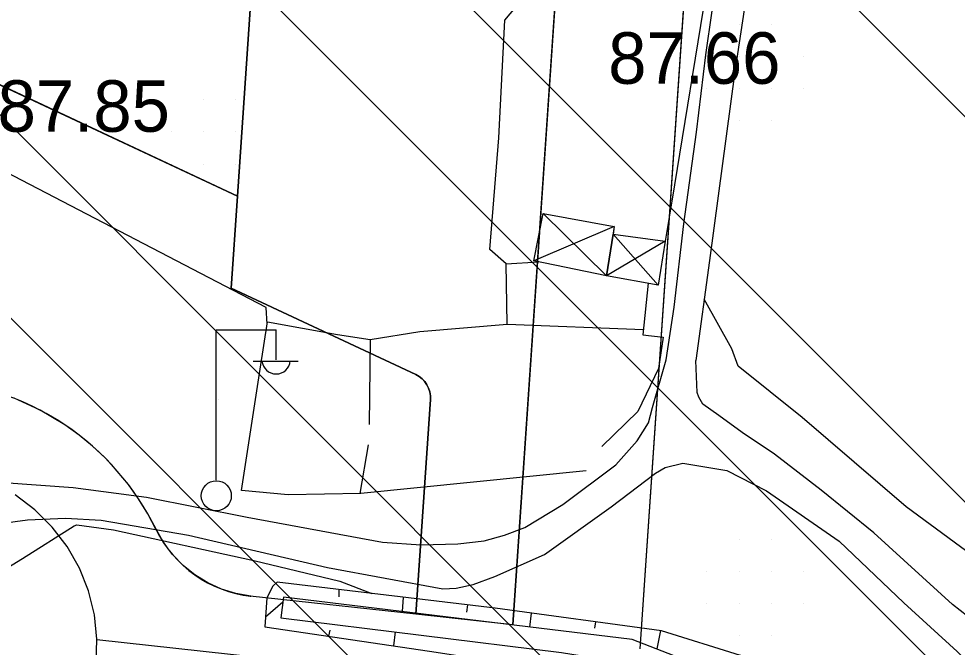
# Model space of a CAD drawing. Extents: x 417995 to 421451, y 4454518 to 4458015.
# Drawn here: x 420928.1 to 421037.5, y 4455671.2 to 4455744.4 of the extents above; entities that cross this region are included whole.
import ezdxf

# ---------------------------------------------------------------- set-up
doc = ezdxf.new("R2010")
doc.units = 0
for name, color, linetype in [('ADAKENARI', 7, 'Continuous'), ('B_Betonzemin', 7, 'Continuous'), ('B_Kapi', 7, 'Continuous'), ('B_Sundurma', 7, 'Continuous'), ('KALDIRIM_FAT', 7, 'Continuous'), ('PL_K_BHA', 7, 'Continuous'), ('PL_T_GUNUBIRLIK', 7, 'Continuous'), ('PL_TA_K_OTOPARK', 7, 'Continuous'), ('S_Elektrik_Diregi', 7, 'Continuous'), ('Sev_Sevalti', 7, 'Continuous'), ('Sev_Sevustu', 7, 'Continuous'), ('Sev_Tarama', 7, 'Continuous'), ('Sinir_Cit_bir_taraf', 7, 'Continuous'), ('Sinir_itirazli_Mulkiyet', 7, 'Continuous'), ('Sinir_Tel_bir_taraf', 7, 'Continuous'), ('SN_TR_SIVILASMA', 7, 'Continuous'), ('TRFAT_BHA', 7, 'Continuous'), ('TRFAT_GUNUBİRLİK', 7, 'Continuous'), ('Y_Kot_Noktasi', 7, 'Continuous'), ('Y_Yol_Kotu', 7, 'Continuous'), ('Yol_Toprak_Duz', 7, 'Continuous'), ('Yol_Toprak_Kesik', 7, 'Continuous')]:
    doc.layers.add(name, color=color, linetype=linetype)

msp = doc.modelspace()

# ---------------------------------------------------------------- linework, layer by layer
at = {"layer": 'ADAKENARI'}
for p, q in [((420953.63, 4455723.77), (420963.07, 4455862.75)), ((420985.73, 4455673.85), (420995.32, 4455815.13)), ((421000.57, 4455671.04), (421010.29, 4455814.11)), ((420915.24, 4455741.74), (420953.63, 4455723.77)), ((420952.9, 4455713.07), (420953.63, 4455723.77)), ((420952.9, 4455713.07), (420974.4, 4455703)), ((420976.12, 4455700.08), (420974.43, 4455675.09)), ((420974.43, 4455675.09), (420955.12, 4455677.19)), ((420985.73, 4455673.85), (420974.43, 4455675.09))]:
    msp.add_line(p, q, dxfattribs=at)
for centre, radius, start, end in [((420916.26, 4455671.38), 31, 56.2175, 105.5206), ((420973.13, 4455700.28), 3, 356.1139, 64.9143), ((420916.26, 4455671.38), 31, 26.002, 56.2175), ((420956.71, 4455691.11), 14, 206.002, 263.771)]:
    msp.add_arc(centre, radius, start, end, dxfattribs=at)
at = {"layer": 'B_Betonzemin'}
msp.add_lwpolyline([(421067.72, 4455631.25), (421023.32, 4455660.48), (421015.05, 4455665.86), (421009.41, 4455668.33), (420999.62, 4455672.15), (420958.99, 4455677.06), (420958.67, 4455674.65), (420991.4, 4455670.63), (421000.3, 4455669.19), (421010.57, 4455665.18), (421038.73, 4455646.9), (421060.73, 4455631.09)], dxfattribs=at)
at = {"layer": 'B_Kapi'}
msp.add_lwpolyline([(420925.1, 4455679.46), (420928.57, 4455681.57)], dxfattribs=at)
at = {"layer": 'B_Sundurma'}
for p, q in [((420989.25, 4455721.75), (420996.66, 4455714.48)), ((420997.54, 4455720.24), (420988.18, 4455716.25)), ((421003.49, 4455718.55), (420996.66, 4455714.48)), ((420997.41, 4455719.37), (421002.67, 4455713.42))]:
    msp.add_line(p, q, dxfattribs=at)
for points in [[(420989.25, 4455721.75), (420997.54, 4455720.24), (420996.66, 4455714.48), (420988.18, 4455716.25)], [(420997.41, 4455719.37), (420996.66, 4455714.48), (420988.18, 4455716.25), (420989.25, 4455721.75), (420997.54, 4455720.24)], [(420997.41, 4455719.37), (421003.49, 4455718.55), (421002.67, 4455713.42), (420996.66, 4455714.48)], [(420997.41, 4455719.37), (421003.49, 4455718.55), (421002.67, 4455713.42), (420996.66, 4455714.48)]]:
    msp.add_lwpolyline(points, close=True, dxfattribs=at)
at = {"layer": 'KALDIRIM_FAT'}
for p, q in [((420930.01, 4455687.25), (420927.72, 4455688.98)), ((420932.04, 4455685.23), (420930.01, 4455687.25)), ((420933.78, 4455682.96), (420932.04, 4455685.23)), ((420935.2, 4455680.46), (420933.78, 4455682.96)), ((420936.26, 4455677.8), (420935.2, 4455680.46)), ((420936.95, 4455675.02), (420936.26, 4455677.8)), ((420937.25, 4455672.17), (420936.95, 4455675.02)), ((420937.16, 4455669.3), (420937.25, 4455672.17)), ((420987.8, 4455666.58), (420937.25, 4455672.1))]:
    msp.add_line(p, q, dxfattribs=at)
at = {"layer": 'PL_K_BHA'}
msp.add_lwpolyline([(420915.24, 4455741.74), (420953.63, 4455723.77), (420952.9, 4455713.07), (420974.4, 4455703), (420974.4, 4455703), (420974.79, 4455702.78), (420975.15, 4455702.5), (420975.46, 4455702.18), (420975.71, 4455701.81), (420975.91, 4455701.4), (420976.05, 4455700.98), (420976.12, 4455700.53), (420976.12, 4455700.08), (420976.12, 4455700.08), (420974.43, 4455675.09), (420955.12, 4455677.19), (420955.19, 4455677.19), (420953.45, 4455677.49), (420951.77, 4455678.01), (420950.16, 4455678.73), (420948.66, 4455679.65), (420947.28, 4455680.76), (420946.05, 4455682.02), (420945, 4455683.44), (420944.13, 4455684.97), (420944.13, 4455684.97), (420943.17, 4455686.78), (420942.1, 4455688.51), (420940.91, 4455690.18), (420939.62, 4455691.76), (420938.23, 4455693.26), (420936.74, 4455694.66), (420935.16, 4455695.95), (420933.5, 4455697.14), (420933.5, 4455697.14), (420930.64, 4455698.85), (420927.6, 4455700.23)], dxfattribs=at)
at = {"layer": 'PL_T_GUNUBIRLIK'}
for points in [[(420918.4, 4455889.24), (420925.14, 4455884.18), (420932.12, 4455879.46), (420939.33, 4455875.09), (420946.74, 4455871.07), (420963.07, 4455862.75), (420953.63, 4455723.77), (420915.24, 4455741.74), (420902.71, 4455747.61), (420837.21, 4455780.99), (420826.46, 4455771.47), (420807.44, 4455792.93), (420792.16, 4455812.19), (420746.55, 4455881.28), (420710.3, 4455994.37)], [(421000.57, 4455671.04), (421010.29, 4455814.11), (421010.42, 4455819.17), (421010.13, 4455824.23), (421009.42, 4455829.24), (421008.3, 4455834.18), (421006.77, 4455839.01), (421004.84, 4455843.69), (421002.53, 4455848.19), (420999.85, 4455852.49), (420996.82, 4455856.55), (420993.47, 4455860.34), (420989.81, 4455863.84), (420985.87, 4455867.02), (420981.68, 4455869.87), (420977.27, 4455872.35), (420953.55, 4455884.44), (420946.79, 4455888.1)]]:
    msp.add_lwpolyline(points, dxfattribs=at)
at = {"layer": 'PL_TA_K_OTOPARK'}
msp.add_lwpolyline([(420995.32, 4455815.13), (420985.73, 4455673.85), (420974.43, 4455675.09), (420976.12, 4455700.08), (420976.12, 4455700.08), (420976.12, 4455700.53), (420976.05, 4455700.98), (420975.91, 4455701.4), (420975.71, 4455701.81), (420975.46, 4455702.18), (420975.15, 4455702.5), (420974.79, 4455702.78), (420974.4, 4455703), (420974.4, 4455703), (420952.9, 4455713.07), (420953.63, 4455723.77), (420963.07, 4455862.75)], dxfattribs=at)
at = {"layer": 'S_Elektrik_Diregi'}
for p, q in [((420951.13, 4455690.71), (420951.13, 4455708.21)), ((420951.13, 4455708.21), (420958.13, 4455708.21)), ((420958.13, 4455704.71), (420958.13, 4455708.21)), ((420955.47, 4455704.57), (420960.72, 4455704.57))]:
    msp.add_line(p, q, dxfattribs=at)
msp.add_circle((420951.16, 4455688.88), 1.75, dxfattribs=at)
msp.add_arc((420958.13, 4455704.73), 1.66, 184.8384, 355.1464, dxfattribs=at)
at = {"layer": 'Sev_Sevalti'}
msp.add_lwpolyline([(421060.73, 4455631.09), (421064.37, 4455628.47), (421079.78, 4455617.97), (421080.48, 4455618.07), (421081.95, 4455620.68), (421081.67, 4455621.39), (421067.72, 4455631.25), (421023.32, 4455660.48), (421015.05, 4455665.86), (421009.41, 4455668.33), (420999.62, 4455672.15), (420958.99, 4455677.06), (420958.67, 4455674.65), (420991.4, 4455670.63), (421000.3, 4455669.19), (421010.57, 4455665.18), (421038.73, 4455646.9), (421060.73, 4455631.09)], dxfattribs=at)
at = {"layer": 'Sev_Sevustu'}
msp.add_lwpolyline([(421084.77, 4455617.56), (421084.03, 4455621.15), (421058.97, 4455638.82), (421028.96, 4455658.53), (421012.25, 4455670.27), (421003.07, 4455673.15), (420983.66, 4455675.79), (420958.26, 4455678.82), (420957.73, 4455678.35), (420957.05, 4455677), (420956.83, 4455673.6), (420976.02, 4455670.79), (421002.11, 4455666.78), (421005.9, 4455665.86), (421016.69, 4455659.45), (421046.16, 4455638.4), (421079.97, 4455615.75), (421081.98, 4455615.46), (421083.52, 4455615.87), (421084.77, 4455617.56)], dxfattribs=at)
at = {"layer": 'Sev_Tarama'}
for p, q in [((420965.44, 4455677.97), (420965.44, 4455677.12)), ((420972.95, 4455677.07), (420972.82, 4455675.39)), ((420956.9, 4455674.79), (420958.92, 4455676.53)), ((420980.42, 4455676.18), (420980.33, 4455675.33)), ((420987.88, 4455675.22), (420987.68, 4455673.59)), ((420995.35, 4455674.2), (420995.24, 4455673.45)), ((420964.28, 4455672.51), (420964.43, 4455673.22)), ((420971.84, 4455671.4), (420972.05, 4455673.01)), ((421002.95, 4455673.17), (421002.5, 4455671.03))]:
    msp.add_line(p, q, dxfattribs=at)
at = {"layer": 'Sinir_Cit_bir_taraf'}
for points in [[(421009.97, 4455770.25), (421011.59, 4455769.85), (421008.51, 4455749.18), (421004.26, 4455723.19)], [(420984.94, 4455715.9), (420983.04, 4455717.55), (420984.1, 4455730.59), (420984.79, 4455744.27), (420986.05, 4455745.75), (420986.86, 4455758.27), (420988.26, 4455762.12)], [(420957.08, 4455708.88), (420956.97, 4455710.81), (420923.7, 4455728.09), (420914.51, 4455730.8)], [(421004.26, 4455723.19), (421003.49, 4455718.55)], [(420994.27, 4455691.79), (420968, 4455689.14), (420959.55, 4455688.97), (420954.09, 4455689.49), (420956.28, 4455703.63), (420957.12, 4455709.15), (420965.29, 4455707.67), (420969.11, 4455707.07), (420974.87, 4455708.02), (420985.05, 4455708.86), (420984.94, 4455715.9), (420988.72, 4455716.14)], [(421001.51, 4455713.63), (421000.89, 4455707.62), (421003.23, 4455707.37), (421002.72, 4455703.72), (421000.31, 4455698.68), (420996.09, 4455694.63)], [(420985.05, 4455708.86), (421000.95, 4455708.24)], [(420969.11, 4455707.07), (420968.99, 4455697.19)], [(420968.87, 4455694.82), (420967.89, 4455689.14)]]:
    msp.add_lwpolyline(points, dxfattribs=at)
at = {"layer": 'Sinir_itirazli_Mulkiyet'}
msp.add_lwpolyline([(421047.02, 4455676.2), (421031.56, 4455687.58), (421019.46, 4455697.98), (421011.97, 4455703.98), (421011.25, 4455705.98), (421008.03, 4455711.78)], dxfattribs=at)
at = {"layer": 'Sinir_Tel_bir_taraf'}
msp.add_lwpolyline([(420928.57, 4455681.57), (420934.59, 4455685.36), (420934.9, 4455685.51), (420939.18, 4455684.9), (420955.52, 4455681.35), (420965.56, 4455678.95), (420969.28, 4455677.51)], dxfattribs=at)
at = {"layer": 'SN_TR_SIVILASMA'}
for p, q in [((421271.63, 4455499.84), (420239.54, 4456531.93)), ((421271.16, 4455455.4), (420227.3, 4456499.27)), ((421270.93, 4455433.18), (420221.05, 4456483.06)), ((421270.47, 4455388.74), (420206.08, 4456453.13)), ((421270.24, 4455366.53), (420198.6, 4456438.16))]:
    msp.add_line(p, q, dxfattribs=at)
at = {"layer": 'TRFAT_BHA'}
msp.add_line((420951.46, 4455700.09), (420951.46, 4455700.09), dxfattribs=at)
at = {"layer": 'TRFAT_GUNUBİRLİK'}
for p, q in [((421012.1, 4455743.82), (421012.1, 4455743.82)), ((421015.85, 4455743.82), (421015.85, 4455743.82)), ((421008.35, 4455740.07), (421008.35, 4455740.07)), ((421012.1, 4455740.07), (421012.1, 4455740.07)), ((421015.85, 4455740.07), (421015.85, 4455740.07)), ((421019.6, 4455740.07), (421019.6, 4455740.07)), ((421008.35, 4455736.32), (421008.35, 4455736.32)), ((421012.1, 4455736.32), (421012.1, 4455736.32)), ((421015.85, 4455736.32), (421015.85, 4455736.32)), ((421019.6, 4455736.32), (421019.6, 4455736.32)), ((420949.7, 4455735.02), (420949.7, 4455735.02)), ((420953.45, 4455735.02), (420953.45, 4455735.02)), ((421012.1, 4455732.57), (421012.1, 4455732.57)), ((421015.85, 4455732.57), (421015.85, 4455732.57)), ((420945.95, 4455731.27), (420945.95, 4455731.27)), ((420949.7, 4455731.27), (420949.7, 4455731.27)), ((420953.45, 4455731.27), (420953.45, 4455731.27)), ((420945.95, 4455727.52), (420945.95, 4455727.52)), ((420949.7, 4455727.52), (420949.7, 4455727.52)), ((420953.45, 4455727.52), (420953.45, 4455727.52)), ((421012.1, 4455683.82), (421012.1, 4455683.82)), ((421015.85, 4455683.82), (421015.85, 4455683.82)), ((421008.35, 4455680.07), (421008.35, 4455680.07)), ((421012.1, 4455680.07), (421012.1, 4455680.07)), ((421015.85, 4455680.07), (421015.85, 4455680.07)), ((421019.6, 4455680.07), (421019.6, 4455680.07)), ((421008.35, 4455676.32), (421008.35, 4455676.32)), ((421012.1, 4455676.32), (421012.1, 4455676.32)), ((421015.85, 4455676.32), (421015.85, 4455676.32)), ((421019.6, 4455676.32), (421019.6, 4455676.32)), ((421012.1, 4455672.57), (421012.1, 4455672.57)), ((421015.85, 4455672.57), (421015.85, 4455672.57))]:
    msp.add_line(p, q, dxfattribs=at)
at = {"layer": 'Yol_Toprak_Duz'}
for points in [[(421017.05, 4455774.11), (421014.22, 4455755.55), (421011.59, 4455738.32), (421008.66, 4455716.27), (421007.04, 4455704.65)], [(420908.77, 4455678.3), (420910.09, 4455679.64), (420913.13, 4455681.59), (420918.26, 4455683.67), (420923.35, 4455685.3), (420929.17, 4455686.06), (420933.57, 4455686.27), (420937.73, 4455686.02), (420947.92, 4455684.3), (420964.13, 4455680.51), (420977.57, 4455678.04), (420979.11, 4455678.12), (420981.1, 4455678.55), (420983.61, 4455679.48), (420989.41, 4455682.05), (420997.19, 4455687.58), (421002.36, 4455691.5), (421003.47, 4455692.16), (421005.55, 4455692.66)], [(421005.55, 4455692.66), (421010.67, 4455691.82), (421015.3, 4455689.44), (421023.76, 4455683.59), (421031.3, 4455676.41), (421037.52, 4455670.75), (421040.69, 4455667.46), (421045.49, 4455661.66), (421050.25, 4455656.46), (421054.91, 4455652.27), (421063.03, 4455644.05), (421071.2, 4455636.06), (421077.34, 4455629.84), (421083.91, 4455623.35), (421090.4, 4455617.33), (421094.06, 4455613.3), (421099.33, 4455607.43), (421101.09, 4455604.62), (421102.59, 4455601.58)]]:
    msp.add_lwpolyline(points, dxfattribs=at)
at = {"layer": 'Yol_Toprak_Kesik'}
for points in [[(420926.41, 4455690.43), (420934.49, 4455689.84), (420943.04, 4455688.7), (420954.74, 4455686.37), (420970.52, 4455683.46), (420975, 4455683.16), (420979.31, 4455683.27), (420982.37, 4455683.63), (420984.74, 4455684.28), (420987.12, 4455685.19), (420991.56, 4455687.88), (420997.74, 4455692.48), (421000.23, 4455695.27), (421001.53, 4455697.36), (421002.02, 4455699.15), (421003.59, 4455704.72), (421004.51, 4455710.85), (421005.67, 4455720.54), (421007.12, 4455731.24), (421008.21, 4455740.26), (421009.7, 4455750.54), (421011.52, 4455762.49), (421013.61, 4455774.95)], [(421040.74, 4455673), (421039.64, 4455674.1), (421036.97, 4455676.22), (421027.81, 4455684.55), (421021.65, 4455689.52), (421016.24, 4455693.72), (421012.47, 4455696.26), (421009.75, 4455698.24), (421007.89, 4455699.54), (421007.41, 4455700.36), (421007.22, 4455700.92), (421007.04, 4455704.65)]]:
    msp.add_lwpolyline(points, dxfattribs=at)

# ---------------------------------------------------------------- texts
at = {"layer": 'Y_Kot_Noktasi'}
msp.add_text('87.85', height=6, dxfattribs=at).set_placement((420925.67, 4455731.28))
at = {"layer": 'Y_Yol_Kotu'}
msp.add_text('87.66', height=6, dxfattribs=at).set_placement((420996.84, 4455736.87))

doc.saveas('drawing.dxf')
